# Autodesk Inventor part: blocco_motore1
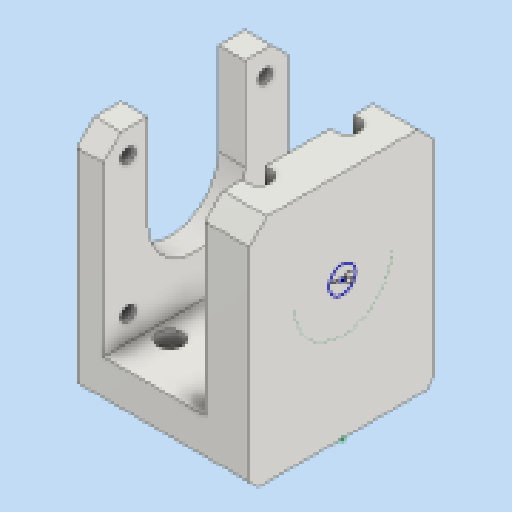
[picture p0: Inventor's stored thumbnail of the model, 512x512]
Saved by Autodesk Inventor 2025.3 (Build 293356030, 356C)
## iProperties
Created: 2025-11
Part Number: blocco_motore1
Material: Plastica ABS
Document SubType Name: Modeling
Designer: R5800u
Density: 1.06 g/cm^3
Appearance: Acciaio
Author: R5800u
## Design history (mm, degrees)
sketch "Schizzo1"
  geometry: L1 (0, 0)-(-15, 0); L2 (-15, 0)-(-15, 52); L3 (-15, 52)-(0, 52); L4 (0, 52)-(0, 0); L5 (-15, 0)-(-47, 0); L6 (-47, 0)-(-47, 10); L7 (-47, 10)-(-15, 10); L8 (-15, 10)-(-15, 0); 1 further point
  constraints: 16 end point, 4 parallel, 2 horizontal, 2 perpendicular
  dimensions: "d0" = 15 distance of L2.end L3.end; "d1" = 52 distance of L1.end L2.end; "d2" = 32 distance of L6.end L7.end; "d3" = 10 distance of L5.end L6.end
extrude "Estrusione1" new body sketch "Schizzo1" stored distance "d4" = 42; taper "d5" = 0 deg
sketch "Schizzo2"
  geometry: L1 (0, 42)-(0, 0) reference; L2 (0, 21)-(32, 21); L3 (32, 42)-(32, 0) reference; C1 r 1.25 at (26.1, 31); C2 r 1.25 at (26.1, 11); C3 r 1.25 at (6.1, 11); C4 r 1.25 at (6.1, 31); 1 further point
  constraints: 4 centre point, 2 end point, 2 midpoint, 1 other
  dimensions: "d31" = 20 distance of C4.centre C3.centre; "d32" = 20 distance of C1.centre C2.centre; "d33" = 20 distance of C2.centre C3.centre; "d34" = 20 distance of C1.centre C4.centre; "d35" = 6.1 distance from line of L1 C3.centre
hole "Foro1" sketch "Schizzo2" at (6.1, 31), (6.1, 11), (26.1, 11), (26.1, 31) diameter "d9" = 2.9; stored, may be unused: countersink angle "d13" = 90 deg, drill point angle "d15" = 118 deg; dims "d10" = 6, "d11" = 5.5, "d12" = 2.9, "d14" = 8
sketch "Schizzo3"
  geometry: C1 r 1.45 at (6.1, 11) reference; C2 r 1.45 at (6.1, 31) reference; C3 r 1.45 at (26.1, 11) reference; C4 r 1.45 at (26.1, 31) reference; 5 further points
  constraints: 4 coincident
hole "Foro2" sketch "Schizzo3" at (6.1, 11), (6.1, 31), (26.1, 11), (26.1, 31) diameter "d16" = 2.9; stored, may be unused: countersink angle "d20" = 90 deg, drill point angle "d22" = 118 deg; dims "d17" = 6, "d18" = 5.5, "d19" = 3.5, "d21" = 8
sketch "Schizzo4"
  geometry: C1 r 1.5 at (10, 15.05) reference; C2 r 1.5 at (17, 8.05) reference; C3 r 1.5 at (17, 22.05) reference; C4 r 1.5 at (24, 15.05) reference; 1 further point
hole "Foro3" sketch "Schizzo4" at (10, 15.05), (17, 8.05), (24, 15.05), (17, 22.05) diameter "d23" = 3.4; stored, may be unused: countersink angle "d27" = 90 deg, drill point angle "d29" = 118 deg; dims "d24" = 6, "d25" = 6.5, "d26" = 3.4, "d28" = 8
sketch "Schizzo5"
  geometry: L1 (0, 0)-(-42, 0) reference; L2 (0, 10)-(0, 0) reference; L3 (-42, 10)-(0, 10) reference; L4 (-42, 0)-(-42, 10) reference; 1 further point
extrude "Estrusione2" join sketch "Schizzo5" distance "d36" = 4; taper "d37" = 0 deg
sketch "Schizzo6"
  geometry: L1 (-36, 0)-(-36, 42) reference; L2 (0, 42)-(0, 0) reference; L3 (0, 0)-(-36, 0) reference; L4 (0, 42)-(-36, 42) reference; L5 (-36, 0)-(-30, 0); L6 (-30, 0)-(-30, 42); L7 (-30, 42)-(-36, 42); L8 (-36, 42)-(-36, 0); L9 (0, 42)-(-36, 42) reference; L10 (0, 0)-(-7, 0); L11 (-7, 0)-(-7, 42); L12 (-7, 42)-(0, 42); L13 (0, 42)-(0, 0); 4 further points
  constraints: 16 end point, 4 parallel, 2 horizontal, 2 perpendicular, 2 point on line
extrude "Estrusione3" join sketch "Schizzo6" distance "d38" = 42; taper "d39" = 0 deg
sketch "Schizzo7"
  geometry: C1 r 1.45 at (24.1, -31) reference; C2 r 2.75 at (24.1, -31); C3 r 2.75 at (24.1, -11); A1 r 2.75 centre (24.1, -31) between (23, -28.48) and (23, -33.52) reference; A2 r 2.75 centre (24.1, -11) between (23, -8.48) and (23, -13.52) reference; A3 r 2.75 centre (24.1, -11) between (23, -13.52) and (23, -8.48) reference; 3 further points
  constraints: 2 centre point, 2 coincident, 1 concentric
extrude "Estrusione4" cut sketch "Schizzo7" distance "d40" = 42; taper "d41" = 0 deg
sketch "Schizzo8"
  geometry: L1 (0, 52)-(-42, 52) reference; L2 (-10, 31.15)-(-32, 31.15); L3 (-32, 31.15)-(-32, 52); L4 (-32, 52)-(-10, 52); L5 (-10, 52)-(-10, 31.15); 4 further points
  constraints: 8 end point, 2 parallel, 1 horizontal, 1 perpendicular, 1 point on line, 2 other
extrude "Estrusione5" cut sketch "Schizzo8" stored distance "d42" = 42; taper "d43" = 0 deg
sketch "Schizzo9"
  geometry: L1 (-32, 31.15)-(-32, 52) reference; L2 (-42, 52)-(-32, 52) reference; L3 (-42, 0)-(-42, 52) reference; L4 (-42, 0)-(0, 0) reference; L5 (0, 0)-(0, 52) reference; L6 (-10, 52)-(0, 52) reference; L7 (-10, 52)-(-10, 31.15) reference; A1 r 11 centre (-21, 31.15) between (-32, 31.15) and (-10, 31.15) reference; 1 further point
extrude "Estrusione6" join sketch "Schizzo9" distance "d44" = 4; taper "d45" = 0 deg
sketch "Schizzo10"
  geometry: L1 (0, 0)-(0, 52) reference; L2 (42, 0)-(0, 0) reference; L3 (42, 0)-(42, 52) reference; L4 (0, 52)-(42, 52) reference; 1 further point
extrude "Estrusione7" join sketch "Schizzo10" distance "d46" = 3; taper "d47" = 0 deg
chamfer "Smusso2" distance "d48" = 2; stored, may be unused: second distance "d49" = 2, angle "d50" = 45 deg
sketch "Schizzo11"
  geometry: C1 r 1.25 at (-5.5, 46.65) reference; C2 r 1.25 at (-36.5, 46.65) reference; C3 r 1.25 at (-36.5, 15.65) reference; C4 r 1.25 at (-5.5, 15.65) reference; 1 further point
hole "Foro4" sketch "Schizzo11" at (-5.5, 15.65), (-5.5, 46.65), (-36.5, 46.65), (-36.5, 15.65) diameter "d51" = 3.2; stored, may be unused: countersink angle "d55" = 90 deg, drill point angle "d57" = 118 deg; dims "d52" = 6, "d53" = 6, "d54" = 1.5, "d56" = 12
chamfer "Smusso3" distance "d58" = 4; stored, may be unused: second distance "d59" = 2, angle "d60" = 45 deg
sketch "Schizzo12"
  geometry: C1 r 3 at (21, 31.15); A1 r 11 centre (21, 31.15) between (10, 31.15) and (32, 31.15) reference; 1 further point
  constraints: 1 centre point, 1 coincident
  dimensions: "d61" = 6 diameter of C1
extrude "Estrusione8" join sketch "Schizzo12" distance "d62" = 4; taper "d63" = 0 deg
node "Solido1"
node "Riferimento5"
node "Riferimento6"
node "Riferimento7"
node "Riferimento8"
node "Linea chiusa proiettata1"
node "Riferimento10"
node "Linea chiusa proiettata2"
node "Linea chiusa proiettata3"
node "Riferimento11"
node "Riferimento12"
node "Riferimento13"
node "Riferimento14"
